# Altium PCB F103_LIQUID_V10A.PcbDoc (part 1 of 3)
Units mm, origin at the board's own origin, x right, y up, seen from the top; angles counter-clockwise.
Board outline 150.1 x 90.1 mm, 2 copper layers (TOP, BOTTOM), stack 1.6 mm thick; 78 components, 80 nets, 341 pads, 418 vias.
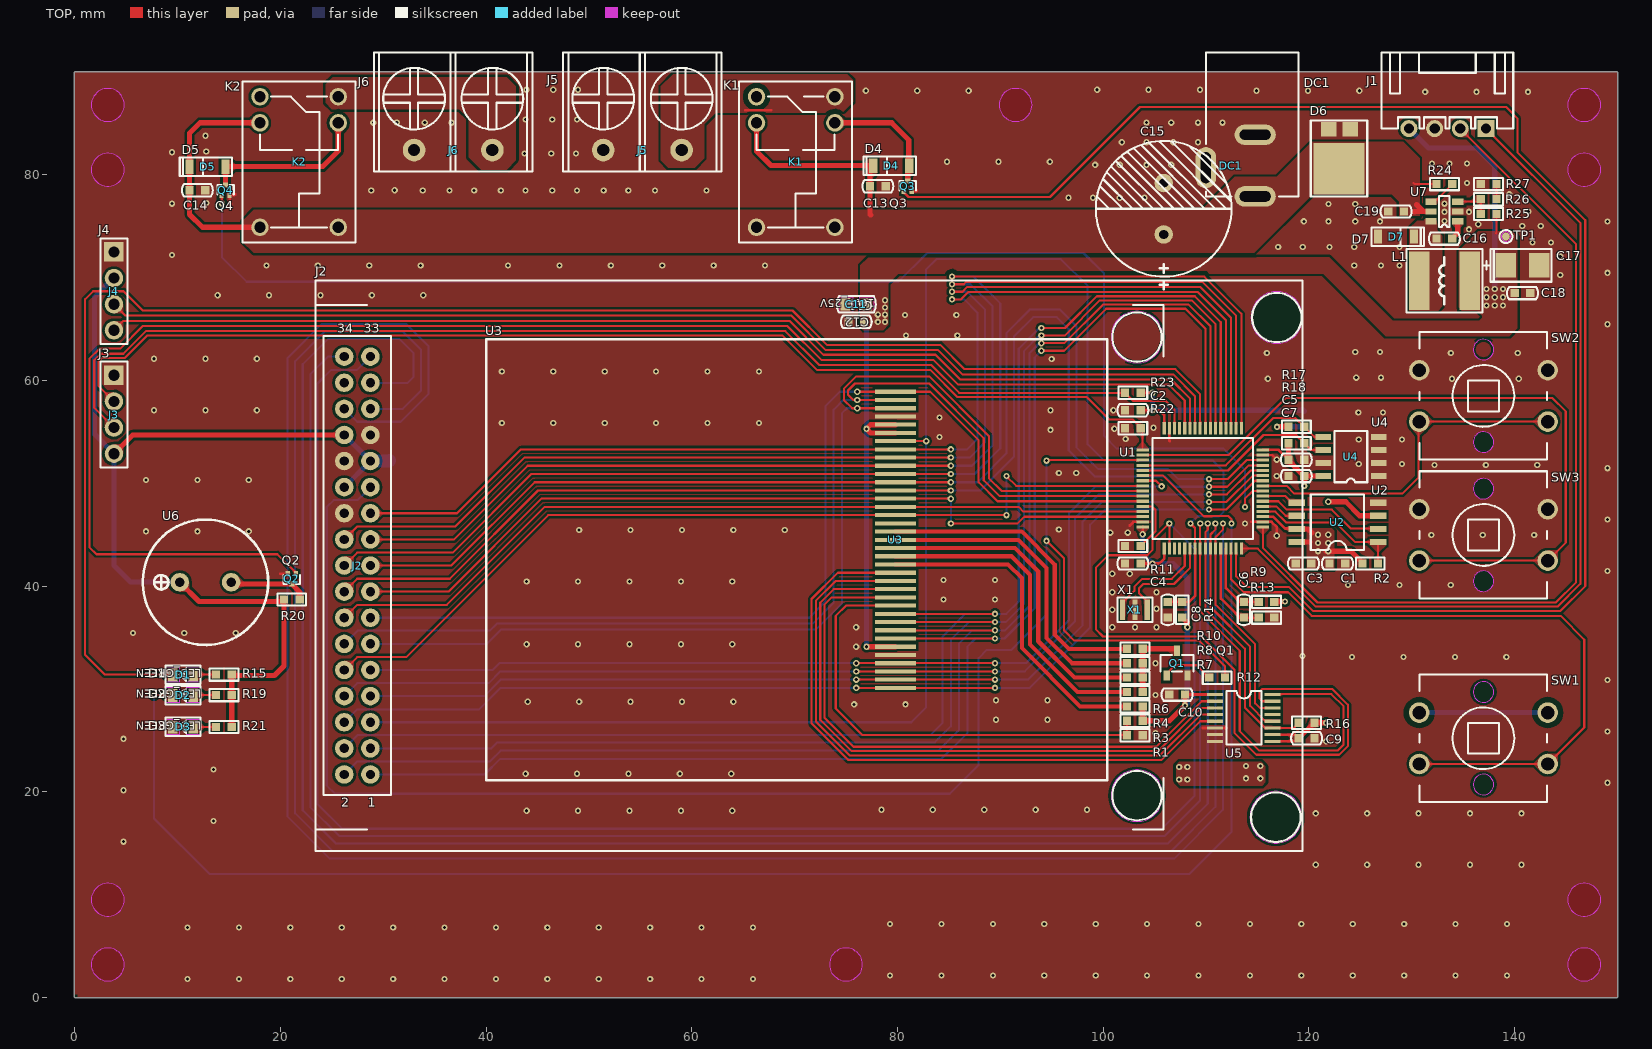
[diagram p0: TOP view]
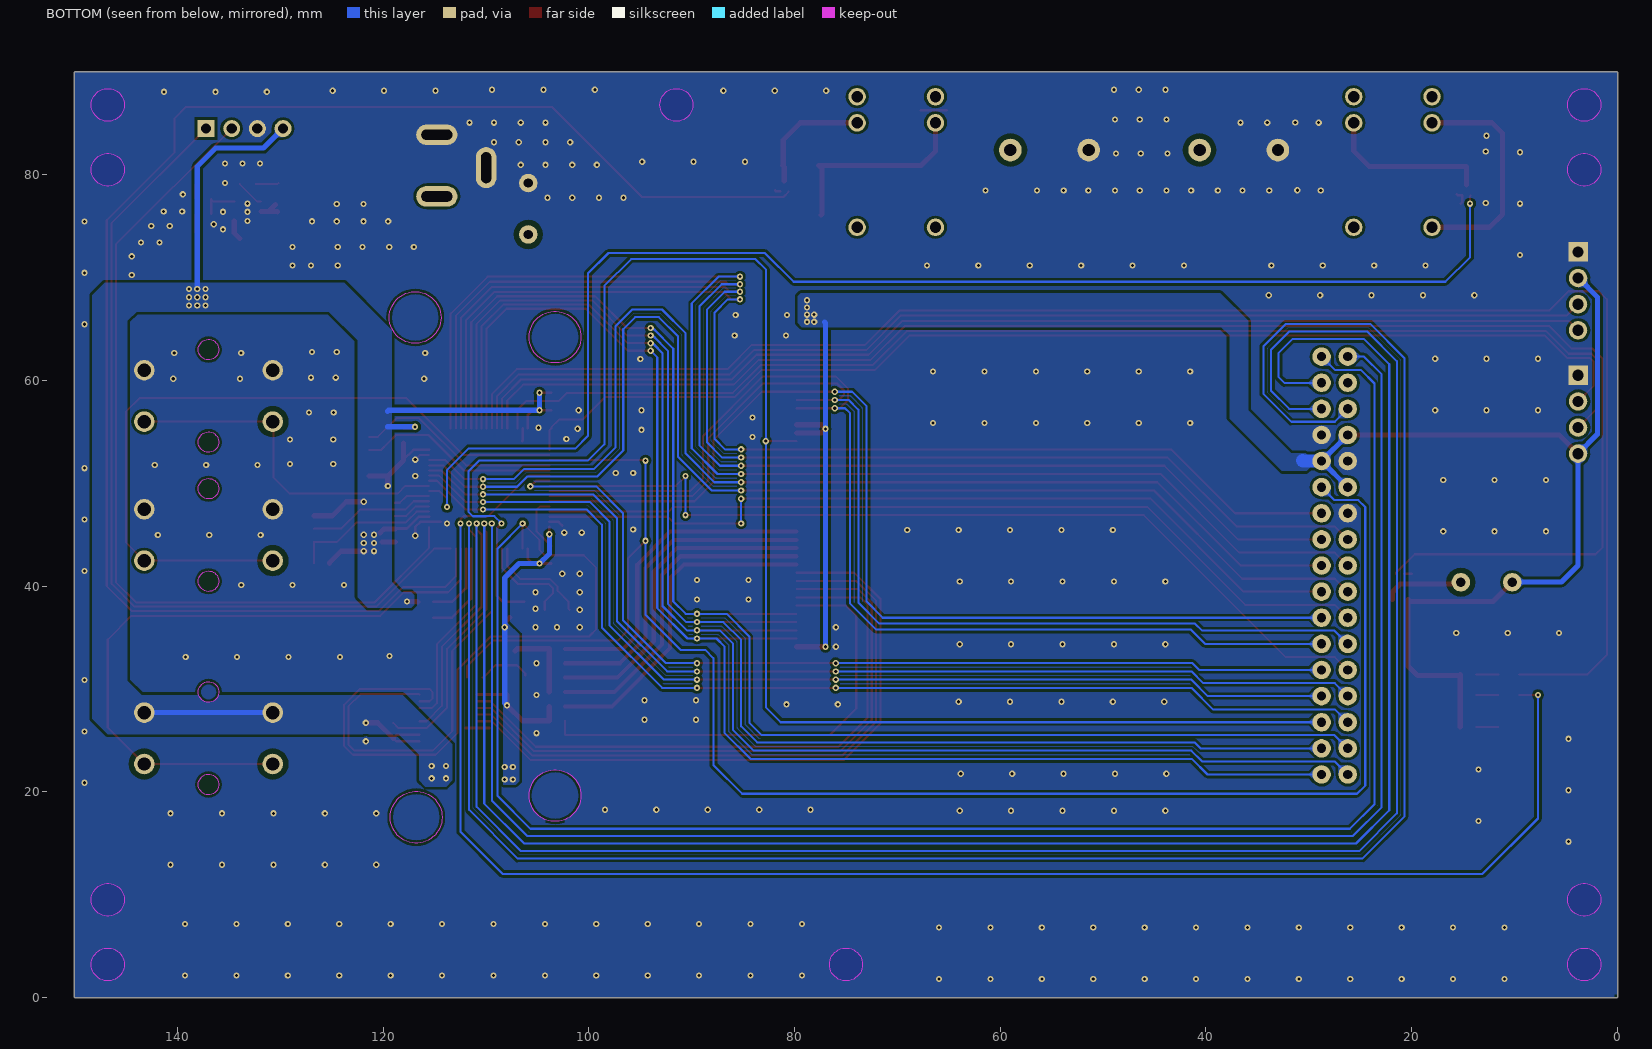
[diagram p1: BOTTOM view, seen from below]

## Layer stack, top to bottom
Top Solder: solder mask 0.0102, Solder Resist, Dk 3.5
TOP: signal copper 0.035
Dielectric 1: core 1.53, FR-4, Dk 4.5
BOTTOM: signal copper 0.035
Bottom Solder: solder mask 0.0102, Solder Resist, Dk 3.5

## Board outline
-0.05,0 0,-0.05 150,-0.05 150.05,0 150.05,90 150,90.05 0,90.05 -0.05,90
cut-out: 4.8,86.8 ccw(c3.2,86.8)
cut-out: 148.4,3.2 ccw(c146.8,3.2)
cut-out: 4.8,80.5 ccw(c3.2,80.5)
cut-out: 4.8,3.2 ccw(c3.2,3.2)
cut-out: 4.8,9.5 ccw(c3.2,9.5)
cut-out: 76.6,3.2 ccw(c75,3.2)
cut-out: 93.1,86.8 ccw(c91.5,86.8)
cut-out: 148.4,86.8 ccw(c146.8,86.8)
cut-out: 148.4,9.5 ccw(c146.8,9.5)
cut-out: 148.4,80.5 ccw(c146.8,80.5)

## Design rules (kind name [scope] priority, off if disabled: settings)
Clearance [All] p1: gap=0.254 ignorepadtopadclearanceinfootprint=FALSE except(0: Arc-Hole Track-Hole SMDPad-Hole THPad-Hole Via-Hole Fill-Hole Poly-Hole Region-Hole Text-Hole)
PlaneConnect [All] p1: planeconnectstyle=Direct reliefexpansion=0.508 reliefentries=4 reliefconductorwidth=0.254 reliefairgap=0.254
PolygonConnect [All] p1: connectstyle=Direct reliefconductorwidth=0.254 reliefentries=4 polygonreliefangle="90 Angle" airgapwidth=0.254
RoutingVias [All] p1: holewidth=0.711 width=1.27 viastyle="Through Hole" minholewidth=0.711 minwidth=1.27 maxholewidth=0.711 maxwidth=1.27
SolderMaskExpansion [All] p1: expansion=0.102
Width [All] p1: maxlimit=0.254 minlimit=0.254 preferedwidth=0.254 impedanceprofiledriven=TRUE minimp=61.210000 maximp=61.210000 favimp=61.210000
29 further rules are at their usual default settings.

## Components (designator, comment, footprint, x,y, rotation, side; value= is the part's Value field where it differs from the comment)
C1 "CAP NP_2_C0603_0.1UF_50V" C0603 122.8,42.2 r0 top
C2 "CAP NP_2_C0603_0.1UF_50V" C0603 102.9,57.1 r0 top
C3 "CAP NP_2_C0603_0.1UF_50V" C0603 119.5,42.2 r0 top
C4 "CAP NP_2_C0603_0.1UF_50V" C0603 102.9,42.2 r0 top
C5 "CAP NP_2_C0603_0.1UF_50V" C0603 118.8,52.3 r180 top
C6 "CAP NP_2_C0603_0.1UF_50V" C0603 113.7,37.7 r90 top
C7 "CAP NP_3_C0603_0.1UF_50V" C0603 118.8,50.7 r0 top
C8 "CAP NP_C0603_0.1UF_50V" C0603 106.3,37.7 r270 top
C9 "CAP NP_C0603_0.1UF_50V" C0603 119.8,25.202 r180 top
C10 "CAP NP_C0603_0.1UF_50V" C0603 107.2,29.452 r180 top
C11 "C_GENERIC_C0805_10UF_25V" C0805 76,67.4 r180 top
C12 "CAP NP_C0603_0.1UF_50V" C0603 76,65.7 r180 top
C13 "CAP NP_C0603_0.1UF_50V" C0603 78.1,78.9 r0 top
C14 "CAP NP_C0603_0.1UF_50V" C0603 11.912,78.5 r0 top
C15 "CAPT_100UF_3528_6R3V_10%_LXXXX_" CAP-5R0-13X27 105.9,76.7 r90 top
C16 "CAP NP_2_C0603_10NF_50V" C0603 133.2,73.8 r180 top
C17 "TMP_154254_C3528B_47UF_10V" C3528B 140.8,71.2 r180 top
C18 "CAP NP_C0603_0.1UF_25V" C0603 140.8,68.5 r0 top
C19 "CAP NP_C0603_0.1UF_25V" C0603 128.5,76.44 r180 top
D1 "LED_4_LED0805_LED_GREEN" LED0805 10.52,31.394 r180 top
D2 "LED_4_LED0805_LED_GREEN" LED0805 10.52,29.4 r180 top
D3 "LED_4_LED0805_LED_GREEN" LED0805 10.52,26.3 r180 top
D4 "DIODE13_7_SOD123_1N4148W-TP" SOD123 79.4,80.9 r0 top
D5 "DIODE13_7_SOD123_1N4148W-TP" SOD123 12.9,80.8 r0 top
D6 "DIODE13_6_TO-227A_V10P10" TO-227A 123,80.6 r180 top
D7 "DIODE13_0_SOD123_LMBR130FT1G" SOD123 128.5,74 r180 top
DC1 "DC005_DC005_DC005" DC005 114.8,83.9 r270 top
J1 "CONN RCPT 4_XHB-4AW_XHB-4AW" XHB-4AW 133.5,84.5 r180 top
J2 "CONN RCPT 17X2_1_TFTLCD_3R5_TFT" TFTLCD_3R5 26.2,62.322 r0 top
J3 "CONN RCPT 4_HEADER4X1-2R54-M_HE" HEADER4X1-2R54-M 3.8,60.5 r270 top
J4 "CONN RCPT 4_HEADER4X1-2R54-M_HE" HEADER4X1-2R54-M 3.8,72.5 r270 top
J5 "HDR_1_KF7R62-2P_KF7R62-2P" KF7R62-2P 55.2,82.412 r0 top
J6 "HDR_1_KF7R62-2P_KF7R62-2P" KF7R62-2P 36.8,82.412 r0 top
K1 "HF32FA-G/005-HSL1_0_HFD41_HFD41" HFD41 66.3,74.9 r90 top
K2 "HF32FA-G/005-HSL1_0_HFD41_HFD41" HFD41 18,74.9 r90 top
L1 "INDUCTOR_0_L6028_SLF6028T-4R7M1" L6028 133.2,69.7 r0 top
Q1 "L14G1/TO_1_SOT23-3_S8050" SOT23-3 107.2,32.5 r0 top
Q2 "DTC043ZMT2L_SOT723_DTC043ZMT2L" SOT723 21.1,40.7 r180 top
Q3 "DTC043ZMT2L_SOT723_DTC043ZMT2L" SOT723 81,78.9 r0 top
Q4 "DTC043ZMT2L_SOT723_DTC043ZMT2L" SOT723 14.65,78.5 r0 top
R1 "R_GENERIC_R0603_0R/NI" R0603 103.1,25.5 r0 top
R2 "R_GENERIC_R0603_10K" R0603 125.988,42.2 r0 top
R3 "R_GENERIC_R0603_0R/NI" R0603 103.1,26.9 r0 top
R4 "R_GENERIC_R0603_0R" R0603 103.1,28.3 r0 top
R6 "R_GENERIC_R0603_10R" R0603 103.1,29.7 r0 top
R7 "R_GENERIC_R0603_10R" R0603 103.1,31.1 r0 top
R8 "R_GENERIC_R0603_10R" R0603 103.1,32.5 r0 top
R9 "R_GENERIC_R0603_0R" R0603 115.9,38.462 r0 top
R10 "R_GENERIC_R0603_10R" R0603 103.1,33.9 r0 top
R11 "R_GENERIC_R0603_10K" R0603 102.9,43.9 r180 top
R12 "R_GENERIC_R0603_1K" R0603 111.1,31.1 r180 top
R13 "R_GENERIC_R0603_0R" R0603 115.9,36.938 r0 top
R14 "R_GENERIC_R0603_10K" R0603 107.7,37.7 r90 top
R15 "R_GENERIC_R0603_4.7K" R0603 14.5,31.394 r180 top
R16 "R_GENERIC_R0603_100K" R0603 119.8,26.7 r180 top
R17 "R_GENERIC_R0603_4.7K" R0603 118.8,55.49 r180 top
R18 "R_GENERIC_R0603_4.7K" R0603 118.8,53.9 r180 top
R19 "R_GENERIC_R0603_4.7K" R0603 14.5,29.4 r180 top
R20 "R_GENERIC_R0603_1K" R0603 21.1,38.7 r0 top
R21 "R_GENERIC_R0603_4.7K" R0603 14.5,26.3 r180 top
R22 "R_GENERIC_R0603_4.7K" R0603 102.9,55.35 r0 top
R23 "R_GENERIC_R0603_4.7K" R0603 102.9,58.8 r180 top
R24 "R_GENERIC_R0603_100K" R0603 133.2,79.1 r0 top
R25 "R_GENERIC_R0603_49.9K" R0603 137.5,76.2 r180 top
R26 "R_GENERIC_R0603_6.2K" R0603 137.5,77.64 r0 top
R27 "R_GENERIC_R0603_10K" R0603 137.5,79.1 r180 top
SW1 "SWITCH-SPST-4P_SW-B3F4055_KEY" SW-B3F4055 137,25.2 r0 top
SW2 "SWITCH-SPST-4P_SW-B3F4055_KEY" SW-B3F4055 137,58.5 r0 top
SW3 "SWITCH-SPST-4P_SW-B3F4055_KEY" SW-B3F4055 137,44.973 r0 top
TP1 "TESTPOINT_0_TP-0R75_TESTPOINT" TP-0R75 139.185,74 r0 top
U1 "STM32F103RXT6_LQFP64-10X10X0R5_" LQFP64-10X10X0R5 109.7,49.5 r0 top
U2 "W25QXX_SOIC8_208_W25Q64JVSSIQ" SOIC8_208 122.8,46.2 r90 top
U3 "TFT-2R4_TFT-2R4_TFT-2R4" TFT-2R4 79.8,30.102 r90 top
U4 "AT24C512_SOIC8_AT24C512C-SSHM-T" SOIC8 124.1,52.6 r90 top
U5 "XPT2046_TSSOP16_XPT2046" TSSOP16 113.7,27.177 r270 top
U6 "PS1240P02BT_PS1240P02BT_PS1240P" PS1240P02BT 12.7,40.374 r0 top
U7 "MP2359DJ-LF-Z_SOT23-6_MP2359DJ-" SOT23-6 133.2,76.44 r90 top
X1 "XTAL_5032_0_X-3P-3R2X1R3-SMD_CS" X-3P-3R2X1R3-SMD 103.1,37.7 r0 top

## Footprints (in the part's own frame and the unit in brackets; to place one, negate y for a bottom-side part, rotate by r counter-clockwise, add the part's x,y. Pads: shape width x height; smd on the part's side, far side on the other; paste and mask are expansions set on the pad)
C0603 [mm] "C0603"
  rect 0.8x0.8 smd: 1(-0.762,0) 2(0.762,0)
  silkscreen extent -1.51,-0.6 1.51,0.6, body extent -0.89,-0.38 0.89,0.38, height 3.81
C0805 [mm] "C0805"
  rect 1x1.2 smd: 1(-1.016,0) 2(1.016,0)
  TOP keep-out region: 0.356,0.762 1.676,0.762 1.676,-0.762 0.356,-0.762 0.356,0.762
  TOP keep-out region: -1.676,0.762 -0.356,0.762 -0.356,-0.762 -1.676,-0.762 -1.676,0.762
  silkscreen extent -1.9,-0.8 1.9,0.8, body extent -1,-0.6 1,0.6, height 3.81
C3528B [mm] "C3528B"
  rect 2x2.4 smd: 1(1.615,0) 2(-1.614,0)
  silkscreen extent -2.8,-1.6 3.8,1.6, body extent -1.8,-1.4 1.8,1.4, height 3.81
CAP-5R0-13X27 [mm] "CAP-5R0-13X27"
  round 1.8 / inner round 1.524 / far side round 1.8 hole 0.9: 1(-2.5,0) 2(2.5,0)
  silkscreen extent -7.8,-6.6 6.6,6.6, body extent -6.51,-6.51 6.51,6.51, height 3.81
DC005 [mm] "DC005"
  oval 2x4 / inner round 1.524 / far side oval 2x4 hole 1 slot 3 at 90 deg: 1(6,0) 2(0,0)
  oval 4x2 / inner round 1.524 / far side oval 4x2 hole 3 slot 1 at 90 deg: 3(3.2,-4.8)
  silkscreen extent -8,-4.8 6,4.2, body extent -8,-4.8 6,4.2, height 3.81
HEADER4X1-2R54-M [mm] "HEADER4X1-2R54-M"
  rect 1.9x1.9 / inner round 1.524 / far side rect 1.9x1.9 hole 1.1: 1(0,0)
  round 1.8 / inner round 1.524 / far side round 1.8 hole 1.1: 2(2.54,0) 3(5.08,0) 4(7.62,0)
  silkscreen extent -1.33,-1.8 8.97,1.3, body extent -1.23,-1.2 8.87,1.2, height 3.81
HFD41 [mm] "HFD41"
  round 1.7 / inner round 1.524 / far side round 1.7 hole 1.1: 1(0,-7.62) 2(10.16,-7.62) 3(12.7,-7.62) 4(12.7,0) 5(10.16,0) 6(0,0)
  silkscreen extent -1.5,-9.3 14.2,1.7, body extent -1.5,-9.31 14.2,1.69, height 3.81
KF7R62-2P [mm] "KF7R62-2P"
  round 2.2 / inner round 1.524 / far side round 2.2 hole 1.2: 1(-3.81,0) 2(3.81,0)
  silkscreen extent -7.71,-2.1 7.69,9.5, body extent -7.62,-2 7.58,9.4, height 3.81
L6028 [mm] "L6028"
  rect 2x5.7 smd: 1(-2.45,0) 2(2.45,0)
  silkscreen extent -3.7,-3.1 3.7,3.1, body extent -3,-3 3,3, height 3.81
LED0805 [mm] "LED0805"
  rect 0.9x1.3 smd: 1(-1,0) 2(1,0)
  TOP keep-out region: 0.356,0.762 1.676,0.762 1.676,-0.762 0.356,-0.762 0.356,0.762
  TOP keep-out region: -1.676,0.762 -0.356,0.762 -0.356,-0.762 -1.676,-0.762 -1.676,0.762
  silkscreen extent -1.7,-0.9 1.7,0.9, body extent -1,-0.6 1,0.6, height 3.81
LQFP64-10X10X0R5 [mm] "LQFP64-10X10X0R5"
  rect 0.3x1.2 smd: 1(-3.75,-5.85) 2(-3.25,-5.85) 3(-2.75,-5.85) 4(-2.25,-5.85) 5(-1.75,-5.85) 6(-1.25,-5.85) 7(-0.75,-5.85) 8(-0.25,-5.85) 9(0.25,-5.85) 10(0.75,-5.85) 11(1.25,-5.85) 12(1.75,-5.85) 13(2.25,-5.85) 14(2.75,-5.85) 15(3.25,-5.85) 16(3.75,-5.85) 33(3.75,5.85) 34(3.25,5.85) 35(2.75,5.85) 36(2.25,5.85) 37(1.75,5.85) 38(1.25,5.85) 39(0.75,5.85) 40(0.25,5.85) 41(-0.25,5.85) 42(-0.75,5.85) 43(-1.25,5.85) 44(-1.75,5.85) 45(-2.25,5.85) 46(-2.75,5.85) 47(-3.25,5.85) 48(-3.75,5.85)
  rect 1.2x0.3 smd: 17(5.85,-3.75) 18(5.85,-3.25) 19(5.85,-2.75) 20(5.85,-2.25) 21(5.85,-1.75) 22(5.85,-1.25) 23(5.85,-0.75) 24(5.85,-0.25) 25(5.85,0.25) 26(5.85,0.75) 27(5.85,1.25) 28(5.85,1.75) 29(5.85,2.25) 30(5.85,2.75) 31(5.85,3.25) 32(5.85,3.75) 49(-5.85,3.75) 50(-5.85,3.25) 51(-5.85,2.75) 52(-5.85,2.25) 53(-5.85,1.75) 54(-5.85,1.25) 55(-5.85,0.75) 56(-5.85,0.25) 57(-5.85,-0.25) 58(-5.85,-0.75) 59(-5.85,-1.25) 60(-5.85,-1.75) 61(-5.85,-2.25) 62(-5.85,-2.75) 63(-5.85,-3.25) 64(-5.85,-3.75)
  silkscreen extent -4.9,-7.21 4.9,4.9, body extent -5,-5 5,5, height 3.81
PS1240P02BT [mm] "PS1240P02BT"
  round 1.8 / inner round 1.524 / far side round 1.8 hole 0.9: 1(-2.5,0) 2(2.5,0)
  silkscreen extent -6.1,-6.1 6.1,6.1, body extent -6.11,-6.11 6.11,6.11, height 3.81
R0603 [mm] "R0603"
  rect 0.8x0.8 smd: 1(-0.762,0) 2(0.762,0)
  silkscreen extent -1.4,-0.6 1.4,0.6, body extent -0.89,-0.38 0.89,0.38, height 3.81
SOD123 [mm] "SOD123"
  rect 0.8x1.4 smd: 1(1.75,0) 2(-1.75,0)
  silkscreen extent -2.7,-0.9 2.4,0.9, body extent -1.7,-0.64 1.73,0.64, height 3.81
SOIC8 [mm] "SOIC8"
  rect 0.6x1.5 smd: 1(-1.9,-2.7) 2(-0.63,-2.7) 3(0.64,-2.7) 4(1.91,-2.7) 5(1.91,2.7) 6(0.64,2.7) 7(-0.63,2.7) 8(-1.9,2.7)
  silkscreen extent -2.5,-4.21 2.5,1.6, body extent -2.5,-2 2.5,2, height 3.81
SOIC8_208 [mm] "SOIC8_208"
  rect 0.6x1.6 smd: 1(-1.905,-3.95) 2(-0.635,-3.95) 3(0.635,-3.95) 4(1.905,-3.95) 5(1.905,3.95) 6(0.635,3.95) 7(-0.635,3.95) 8(-1.905,3.95)
  silkscreen extent -2.7,-5.51 2.7,2.6, body extent -2.7,-2.6 2.7,2.6, height 3.81
SOT23-3 [mm] "SOT23-3"
  rect 0.6x1 smd: 1(-1,-1.2) 2(1,-1.2) 3(0,1.2)
  silkscreen extent -1.6,-0.8 1.6,0.8, body extent -1.5,-0.7 1.5,0.7, height 3.81
SOT23-6 [mm] "SOT23-6"
  rect 0.6x1.1 smd: 1(-0.95,-1.3) 2(0,-1.3) 3(0.95,-1.3) 4(0.95,1.3) 5(0,1.3) 6(-0.95,1.3)
  silkscreen extent -1.52,-2.54 1.52,0.51, body extent -1.5,-0.8 1.5,0.8, height 3.81
SOT723 [mm] "SOT723"
  rect 0.4x0.5 smd: 1(-0.4,-0.5) 2(0.4,-0.5)
  rect 0.5x0.5 smd: 3(0,0.5)
  silkscreen extent -0.8,-0.4 0.8,0.5, body extent -0.65,-0.45 0.65,0.45, height 3.81
SW-B3F4055 [mm] "SW-B3F4055"
  round 2 / inner round 1.524 / far side round 2 hole 1.3: 1(-6.25,2.5) 2(6.25,2.5) 3(-6.25,-2.5) 4(6.25,-2.5)
  Multi-Layer keep-out circle w0.025: c0,-4.5 r1
  Multi-Layer keep-out circle w0.025: c0,4.5 r1
  silkscreen extent -6.2,-6.2 6.2,6.2, body extent -6,-6 6,6, height 3.81
TFT-2R4 [mm] "TFT-2R4"
  rect 0.4x4 smd: 1(0,0) 2(0.8,0) 3(1.6,0) 4(2.4,0) 5(3.2,0) 6(4,0) 7(4.8,0) 8(5.6,0) 9(6.4,0) 10(7.2,0) 11(8,0) 12(8.8,0) 13(9.6,0) 14(10.4,0) 15(11.2,0) 16(12,0) 17(12.8,0) 18(13.6,0) 19(14.4,0) 20(15.2,0) 21(16,0) 22(16.8,0) 23(17.6,0) 24(18.4,0) 25(19.2,0) 26(20,0) 27(20.8,0) 28(21.6,0) 29(22.4,0) 30(23.2,0) 31(24,0) 32(24.8,0) 33(25.6,0) 34(26.4,0) 35(27.2,0) 36(28,0) 37(28.8,0)
  silkscreen extent -9,-20.6 33.9,39.8, body extent -8.9,-20.5 33.8,39.7, height 3.81
TFTLCD_3R5 [mm] "TFTLCD_3R5"
  round 1.8 / inner round 1.524 / far side round 1.8 hole 0.9: 1(2.54,-40.64) 2(0,-40.64) 3(2.54,-38.1) 4(0,-38.1) 5(2.54,-35.56) 6(0,-35.56) 7(2.54,-33.02) 8(0,-33.02) 9(2.54,-30.48) 10(0,-30.48) 11(2.54,-27.94) 12(0,-27.94) 13(2.54,-25.4) 14(0,-25.4) 15(2.54,-22.86) 16(0,-22.86) 17(2.54,-20.32) 18(0,-20.32) 19(2.54,-17.78) 20(0,-17.78) 21(2.54,-15.24) 22(0,-15.24) 23(2.54,-12.7) 24(0,-12.7) 25(2.54,-10.16) 26(0,-10.16) 27(2.54,-7.62) 28(0,-7.62) 29(2.54,-5.08) 30(0,-5.08) 31(2.54,-2.54) 32(0,-2.54) 33(2.54,0) 34(0,0)
  Multi-Layer keep-out circle w0.025: c90.6,-44.8 r2.518
  Multi-Layer keep-out circle w0.025: c77.1,-42.7 r2.518
  Multi-Layer keep-out circle w0.025: c90.7,3.8 r2.518
  Multi-Layer keep-out circle w0.025: c77.1,1.9 r2.518
  silkscreen extent -2.8,-48.1 93.2,7.4, body extent -1.78,-42.55 4.44,1.91, height 3.81
TO-227A [mm] "TO-227A"
  rect 1.5x1.4 smd: 1(1.04,-3.85) 2(-1.04,-3.85)
  rect 5x5 smd: 3(0.05,0)
  silkscreen extent -2.7,-4.7 2.8,2.7, body extent -2.15,-4.1 2.2,2.05, height 3.81
TP-0R75 [mm] "TP-0R75"
  round 0.75 smd: 1(0,0)
  TOP keep-out circle w0.025: c0,0 r0.457
  silkscreen extent -0.63,-0.63 0.64,0.63, body extent -0.47,-0.47 0.47,0.47, height 3.81
TSSOP16 [mm] "TSSOP16"
  rect 0.3x1.55 smd: 1(-2.275,-2.8) 2(-1.625,-2.8) 3(-0.975,-2.8) 4(-0.325,-2.8) 5(0.325,-2.8) 6(0.975,-2.8) 7(1.625,-2.8) 8(2.275,-2.8) 9(2.275,2.8) 10(1.625,2.8) 11(0.975,2.8) 12(0.325,2.8) 13(-0.325,2.8) 14(-0.975,2.8) 15(-1.625,2.8) 16(-2.275,2.8)
  silkscreen extent -2.6,-4.31 2.6,1.7, body extent -2.5,-1.7 2.5,1.7, height 3.81
X-3P-3R2X1R3-SMD [mm] "X-3P-3R2X1R3-SMD"
  rect 0.5x2 smd: 1(-1.2,0) 2(0,0) 3(1.2,0)
  silkscreen extent -1.7,-1.2 1.7,1.2, body extent -1.6,-0.65 1.6,0.65, height 3.81
XHB-4AW [mm] "XHB-4AW"
  rect 1.65x1.65 / inner round 1.524 / far side rect 1.65x1.65 hole 1: 1(-3.75,0)
  round 1.65 / inner round 1.524 / far side round 1.65 hole 1: 2(-1.25,0) 3(1.25,0) 4(3.75,0)
  silkscreen extent -6.4,-7.4 6.4,0, body extent -6.3,-7.3 6.3,-0.1, height 3.81

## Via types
v1: diameter 0.61, hole 0.305, TOP to BOTTOM, tented both sides, 418 vias

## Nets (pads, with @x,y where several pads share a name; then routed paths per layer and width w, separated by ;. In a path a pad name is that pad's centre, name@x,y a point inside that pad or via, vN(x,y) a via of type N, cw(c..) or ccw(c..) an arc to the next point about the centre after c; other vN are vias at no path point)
BOOT0: R11.1 U1.60 | length 5.5
  TOP w0.203: R11.1@103.662,43.9 105.1,45.338 105.1,47.4 104.75,47.75 U1.60@103.85,47.75
CTL_BEEP: Q2.1 U1.44 | length 153.1
  TOP w0.203: Q2.1@21.5,41.2 21.5,41.281 19.681,43.1 2.1,43.1 1.406,43.794 1.406,62.106 2.4,63.1 4.4,63.1 6.6,65.3 69.3,65.3 72.6,62 83.5,62 85.9,59.6 106.4,59.6 107.95,58.05 U1.44@107.95,55.35
CTL_RELAY1: Q3.1 U1.15 | length 151.3
  TOP w0.203: Q3.1@80.6,78.4 80.6,78.319 81.074,77.845 94.845,77.845 103.6,86.6 139.2,86.6 140.3,85.5 140.3,82.2 146.9,75.6 146.9,40 144.494,37.594 120.406,37.594 118.1,39.9 114,39.9 112.95,40.95 U1.15@112.95,43.65
CTL_RELAY2: Q4.1 U1.24 | length 132.1
  TOP w0.203: Q4.1@14.25,78 14.3,77.95 v1(14.3,77.2) ; v1(113.8,47.7) 113.8,48.5 114.55,49.25 U1.24@115.55,49.25
  BOTTOM w0.203: v1(14.3,77.2) 14.3,72 16.7,69.6 80.1,69.6 82.9,72.4 98.1,72.4 100.1,70.4 100.1,54.6 101.3,53.4 111.7,53.4 113.8,51.3 v1(113.8,47.7)
F_CS: R2.2 U1.20 U2.1 | length 14.5
  TOP w0.203: U1.20@115.55,47.25 116.75,47.25 117.8,46.2 122.6,46.2 124.5,44.3 126.745,44.3 U2.1@126.75,44.295 R2.2@126.75,42.2
GND: C1.2 C2.1 C3.1 C4.1 C5.1 C7.1 C8.2 C9.1 C10.2 C11.2 C12.2 C13.2 C14.2 C15.2 C17.2 C18.2 C19.2 D3.2 D6.1 D6.2 D7.1 DC1.2 DC1.3 J1.3 J2.22 J2.26 J2.27 J3.1 J4.1 J5.1 J6.1 Q1.2 Q2.2 Q3.2 Q4.2 R1.2 R11.2 R13.2 R22.1 R27.2 SW2.1 SW2.2 SW3.1 SW3.2 U1.18 U1.31 U1.47 U1.63 U2.4 U3.5 U3.34 U4.1 U4.2 U4.3 U4.4 U4.7 U5.6 U5.7 U5.8 U7.2 X1.2 | length 12.7
  TOP w0.203: U1.31@115.55,52.75 116.45,52.75 v1(116.9,52.3)
  TOP w0.254: 15.2,77.2 15.05,77.35 Q4.2@15.05,78 15.5,78 15.6,78.1 ; 20,41.2 Q2.2@20.7,41.2 ; Q3.2@81.4,78.4 81.8,78.4 81.9,78.5 ; 102.6,45.9 102.95,46.25 U1.63@103.85,46.25 ; U1.47@106.45,55.35 106.45,54.15 106.5,54.1 ; 109.7,26.2 109.702,26.202 U5.6@110.9,26.202 111.998,26.202 112,26.2 ; 114.409,46.25 U1.18@115.55,46.25 116.403,46.25 116.9,45.753 v1(116.9,44.9)
  other v1: 10.954,1.791 15.954,1.791 20.954,1.791 25.954,1.791 30.954,1.791 35.954,1.791 40.954,1.791 45.954,1.791 50.954,1.791 55.954,1.791 60.954,1.791 65.954,1.791 79.287,2.128 84.287,2.128 89.287,2.128 94.287,2.128 99.287,2.128 104.287,2.128 109.287,2.128 114.287,2.128 119.287,2.128 124.287,2.128 129.287,2.128 134.287,2.128 139.287,2.128 10.954,6.791 15.954,6.791 20.954,6.791 25.954,6.791 30.954,6.791 35.954,6.791 40.954,6.791 45.954,6.791 50.954,6.791 55.954,6.791 60.954,6.791 65.954,6.791 79.287,7.128 84.287,7.128 89.287,7.128 94.287,7.128 99.287,7.128 104.287,7.128 109.287,7.128 114.287,7.128 119.287,7.128 124.287,7.128 129.287,7.128 134.287,7.128 139.287,7.128 120.69,12.9 125.69,12.9 130.69,12.9 135.69,12.9 140.69,12.9 4.727,15.144 13.479,17.163 120.69,17.9 125.69,17.9 130.69,17.9 135.69,17.9 140.69,17.9 43.943,18.146 48.943,18.146 53.943,18.146 58.943,18.146 63.943,18.146 78.442,18.246 83.443,18.246 88.443,18.246 93.443,18.246 98.443,18.246 4.727,20.144 149.074,20.87 43.843,21.746 48.843,21.746 53.843,21.746 58.843,21.746 63.843,21.746 13.479,22.163 121.7,24.9 4.727,25.144 105.1,25.7 149.074,25.87 89.59,27 94.59,27 75.79,28.5 80.79,28.5 44.043,28.746 49.043,28.746 54.043,28.746 59.043,28.746 64.043,28.746 89.59,28.9 94.59,28.9 105.1,29.4 149.074,30.87 105.1,32.5 124.225,33.096 129.225,33.096 134.225,33.096 139.225,33.096 119.4,33.2 75.99,34.1 43.943,34.346 48.943,34.346 53.943,34.346 58.943,34.346 63.943,34.346 5.643,35.446 10.643,35.446 15.643,35.446 75.99,36 100.9,36 103.1,36 105.2,36 100.9,37.7 105.2,37.8 84.49,38.7 89.49,38.7 100.9,39.4 105.2,39.4 123.825,40.096 128.825,40.096 133.825,40.096 43.943,40.446 48.943,40.446 53.943,40.446 58.943,40.446 63.943,40.446 84.49,40.6 89.49,40.6 100.9,41.2 102.6,41.2 149.074,41.47 131.93,44.974 136.93,44.974 141.93,44.974 100.7,45.2 102.4,45.2 6.915,45.327 11.915,45.327 16.915,45.327 49.043,45.446 54.043,45.446 59.043,45.446 64.043,45.446 69.043,45.446 95.7,45.5 113.8,46.1 149.074,46.47 6.915,50.327 11.915,50.327 16.915,50.327 116.9,50.7 95.7,51 97.4,51 149.074,51.47 132.23,51.774 137.23,51.774 142.23,51.774 124.874,51.87 129.074,51.87 124.874,54.27 129.074,54.27 102.2,54.3 84.09,54.5 94.89,55.2 101.1,55.3 104.9,55.4 41.53,55.874 46.53,55.874 51.53,55.874 56.53,55.874 61.53,55.874 66.53,55.874 84.09,56.4 124.83,56.874 127.23,56.874 7.701,57.108 12.701,57.108 17.701,57.108 94.89,57.1 101,57.1 116.03,60.174 133.93,60.174 140.43,60.174 124.63,60.274 127.03,60.274 41.53,60.874 46.53,60.874 51.53,60.874 56.53,60.874 61.53,60.874 66.53,60.874 7.701,62.108 12.701,62.108 17.701,62.108 95,62.1 115.93,62.674 133.83,62.674 140.33,62.674 124.53,62.774 126.93,62.774 80.83,64.374 85.83,64.374 149.074,65.47 80.73,66.374 85.73,66.374 13.884,68.29 18.884,68.29 23.884,68.29 28.884,68.29 33.884,68.29 144.474,70.27 149.074,70.47 18.63,71.174 23.63,71.174 28.63,71.174 33.63,71.174 42.13,71.174 47.13,71.174 52.13,71.174 57.13,71.174 62.13,71.174 67.13,71.174 124.43,71.174 127.03,71.174 128.83,71.174 144.474,72.07 9.44,72.2 117.03,72.974 119.43,72.974 122.03,72.974 124.43,72.974 128.83,72.974 141.77,73.426 143.57,73.426 135.6,74.7 140.77,75.026 142.57,75.026 136.5,75.2 119.53,75.474 121.93,75.474 124.53,75.474 126.93,75.474 149.074,75.47 133.2,75.5 133.2,76.4 135.6,76.4 139.57,76.426 141.37,76.426 121.93,77.174 124.53,77.174 9.44,77.2 133.2,77.2 12.774,77.27 96.63,77.774 99.03,77.774 101.63,77.774 104.03,77.774 139.5,78.1 28.83,78.474 33.83,78.474 36.43,78.474 38.83,78.474 41.43,78.474 43.83,78.474 46.43,78.474 48.83,78.474 51.43,78.474 53.83,78.474 56.43,78.474 61.43,78.474 31.1,78.5 135.4,79.2 99.23,80.974 101.63,80.974 104.23,80.974 106.63,80.974 132,81.1 133.7,81.1 135.4,81.1 84.83,81.274 89.83,81.274 94.83,81.274 43.73,82.074 46.33,82.074 48.73,82.074 9.44,82.2 12.774,82.27 101.83,83.174 104.23,83.174 106.83,83.174 109.23,83.174 12.7,83.8 29.03,85.074 34.03,85.074 36.63,85.074 104.23,85.074 106.63,85.074 109.23,85.074 111.63,85.074 31.3,85.1 43.83,85.374 46.43,85.374 48.83,85.374 131.33,88.074 136.33,88.074 141.33,88.074 76.93,88.174 81.93,88.174 86.93,88.174 114.93,88.174 119.93,88.174 124.93,88.174 43.93,88.274 46.53,88.274 48.93,88.274 99.43,88.274 104.43,88.274 109.43,88.274
IIC_SCL: R18.1 U1.53 U4.6 | length 19.6
  TOP w0.203: U1.53@103.85,51.25 112.157,51.25 115.604,54.696 118.766,54.696 R18.1@119.562,53.9 120.222,53.24 U4.6@121.4,53.24
IIC_SDA: R17.1 U1.52 U4.5 | length 20.2
  TOP w0.203: U1.52@103.85,51.75 111.95,51.75 116.55,56.35 118.702,56.35 R17.1@119.562,55.49 120.542,54.51 U4.5@121.4,54.51
IM0: R1.1 R3.1 U3.11 | length 46
  TOP w0.203: U3.11@79.8,38.102 75.002,38.102 74,37.1 74,28.1 76.6,25.5 R1.1@102.338,25.5 R3.1@102.338,26.9
KEY0: SW2.3 SW2.4 U1.25 | length 34
  TOP w0.203: U1.25@115.55,49.75 117.85,49.75 118.6,49 129.1,49 130.7,50.6 130.7,55.95 SW2.3@130.75,56 SW2.4@143.25,56
KEY1: SW3.3 SW3.4 U1.50 | length 71.7
  TOP w0.203: U1.50@103.85,52.75 112.231,52.75 117.781,58.3 143.7,58.3 145,57 145,44.224 SW3.4@143.25,42.473 SW3.3@130.75,42.473
LCD_BL: J2.23 R12.1 U1.51 | length 167.8
  TOP w0.203: v1(94.5,44.4) 96.2,42.7 96.2,35.7 97.206,34.694 109.375,34.694 111.862,32.207 R12.1@111.862,31.1 ; v1(94.5,52.2) 94.55,52.25 U1.51@103.85,52.25
  BOTTOM w0.203: J2.23@28.74,49.622 27.484,48.366 25.166,48.366 24.5,47.7 24.5,20.6 25.3,19.8 85.1,19.8 87.9,22.6 87.9,33 88.7,33.8 91.1,33.8 94.5,37.2 v1(94.5,44.4) v1(94.5,52.2)
LCD_CS: J2.1 U1.40 U3.7 | length 139.4
  TOP w0.203: U3.7@79.8,34.902 v1(89.5,34.902) ; v1(94,62.89) 96.212,62.89 100.296,66.974 108.026,66.974 109.95,65.05 U1.40@109.95,55.35
  BOTTOM w0.203: J2.1@28.74,21.682 39.84,21.682 41.358,23.2 84.294,23.2 86.8,25.706 86.8,34.106 87.596,34.902 v1(89.5,34.902) 90.412,34.902 93.362,37.853 93.362,62.253 v1(94,62.89)
LCD_D0: J2.6 U1.26 U3.1 | length 104.9
  TOP w0.203: v1(76,30.102) U3.1@79.8,30.102 v1(89.5,30.102) ; v1(110.3,47.454) 111.982,47.454 114.779,50.25 U1.26@115.55,50.25
  BOTTOM w0.203: J2.6@26.2,26.762 27.456,28.018 39.318,28.018 41.402,30.102 v1(76,30.102) ; v1(89.5,30.102) 92.869,30.102 98.746,35.979 98.746,45.979 100.221,47.454 v1(110.3,47.454)
LCD_D1: J2.7 U1.27 U3.2 | length 101.6
  TOP w0.203: v1(76,30.902) U3.2@79.8,30.902 v1(89.5,30.902) ; v1(110.3,48.19) 112.012,48.19 114.572,50.75 U1.27@115.55,50.75
  BOTTOM w0.203: J2.7@28.74,29.302 39.802,29.302 41.402,30.902 v1(76,30.902) ; v1(89.5,30.902) 92.702,30.902 98.01,36.21 98.01,46.284 99.916,48.19 v1(110.3,48.19)
LCD_D2: J2.8 U1.28 U3.3 | length 104.3
  TOP w0.203: v1(76,31.702) U3.3@79.8,31.702 v1(89.5,31.702) ; v1(110.3,48.927) 112.041,48.927 114.364,51.25 U1.28@115.55,51.25
  BOTTOM w0.203: J2.8@26.2,29.302 27.456,30.558 40.258,30.558 41.402,31.702 v1(76,31.702) ; v1(89.5,31.702) 92.386,31.702 97.273,36.59 97.273,46.59 99.61,48.927 v1(110.3,48.927)
LCD_D3: J2.9 U1.55 U3.4 | length 92.5
  TOP w0.203: v1(76,32.502) U3.4@79.8,32.502 v1(89.498,32.502) ; U1.55@103.85,50.25 105.15,50.25 v1(105.7,49.7)
  BOTTOM w0.203: J2.9@28.74,31.842 40.642,31.842 41.302,32.502 v1(76,32.502) ; v1(89.498,32.502) 92.502,32.502 96.706,36.706 96.706,47.106 99.3,49.7 v1(105.7,49.7)
LCD_D4: J2.10 U1.56 U3.22 | length 88.1
  TOP w0.203: J2.10@26.2,31.842 27.456,33.098 32.231,33.098 46.036,46.902 U3.22@79.8,46.902 v1(90.6,46.902) ; v1(90.6,50.7) 91.55,49.75 U1.56@103.85,49.75
  BOTTOM w0.203: v1(90.6,46.902) v1(90.6,50.7)
LCD_D5: J2.11 U1.57 U3.35 | length 110.7
  TOP w0.203: U3.35@79.8,57.302 v1(76.1,57.302) 75.598,57.302 74.794,58.106 74.794,59.194 76,60.4 83.1,60.4 88.9,54.6 88.9,50.5 90.15,49.25 U1.57@103.85,49.25
  BOTTOM w0.203: J2.11@28.74,34.382 40.082,34.382 41.491,35.791 72.091,35.791 74.6,38.3 74.6,56.799 75.103,57.302 v1(76.1,57.302)
LCD_D6: J2.12 U1.58 U3.36 | length 111.8
  TOP w0.203: U3.36@79.8,58.102 v1(76.1,58.102) 75.698,58.102 75.2,58.6 75.2,59.025 75.875,59.7 83.093,59.7 88.4,54.393 88.4,50.293 89.943,48.75 U1.58@103.85,48.75
  BOTTOM w0.203: J2.12@26.2,34.382 27.484,35.666 40.366,35.666 41.056,36.356 71.756,36.356 73.8,38.4 73.8,57.169 74.733,58.102 v1(76.1,58.102)
LCD_D7: J2.13 U1.59 U3.37 | length 102.2
  TOP w0.203: v1(76.1,58.902) U3.37@79.8,58.902 83.184,58.902 87.9,54.186 87.9,50.086 89.736,48.25 U1.59@103.85,48.25
  BOTTOM w0.203: J2.13@28.74,36.922 71.422,36.922 73,38.5 73,57.5 74.402,58.902 v1(76.1,58.902)
LCD_D8: J2.14 U1.61 U3.23 | length 82.3
  TOP w0.203: J2.14@26.2,36.922 27.456,38.178 36.18,38.178 45.704,47.702 U3.23@79.8,47.702 91.798,47.702 92.25,47.25 U1.61@103.85,47.25
LCD_D9: J2.15 U1.62 U3.24 | length 81.5
  TOP w0.203: J2.15@28.74,39.462 36.333,39.462 45.373,48.502 U3.24@79.8,48.502 v1(85.2,48.502) ; v1(85.2,46.1) 91.7,46.1 92.35,46.75 U1.62@103.85,46.75
  BOTTOM w0.203: v1(85.2,46.1) v1(85.2,48.502)
LCD_D10: J2.16 U1.29 U3.25 | length 121.9
  TOP w0.203: J2.16@26.2,39.462 27.456,40.718 36.457,40.718 45.041,49.302 U3.25@79.8,49.302 v1(85.2,49.302) ; v1(110.3,49.663) 112.071,49.663 114.157,51.75 U1.29@115.55,51.75
  BOTTOM w0.203: v1(85.2,49.302) 88.044,49.302 91.337,52.595 91.337,64.295 93.205,66.163 95.495,66.163 96.663,64.995 96.663,53.195 99.195,50.663 105.995,50.663 106.995,49.663 v1(110.3,49.663)
LCD_D11: J2.17 U1.30 U3.26 | length 118.5
  TOP w0.203: J2.17@28.74,42.002 36.61,42.002 44.71,50.102 U3.26@79.8,50.102 v1(85.2,50.102) ; v1(110.3,50.4) 112.1,50.4 113.95,52.25 U1.30@115.55,52.25
  BOTTOM w0.203: v1(85.2,50.102) 85.202,50.1 87.8,50.1 90.6,52.9 90.6,64.6 92.9,66.9 95.8,66.9 97.4,65.3 97.4,53.5 99.5,51.4 106.3,51.4 107.3,50.4 v1(110.3,50.4)
LCD_D12: J2.18 U1.33 U3.27 | length 129.2
  TOP w0.203: J2.18@26.2,42.002 27.456,43.258 36.734,43.258 44.379,50.902 U3.27@79.8,50.902 v1(85.2,50.902) ; v1(85.3,70.1) 109.85,70.1 113.45,66.5 U1.33@113.45,55.35
  BOTTOM w0.203: v1(85.2,50.902) 87.502,50.902 90,53.4 90,67.5 87.4,70.1 v1(85.3,70.1)
LCD_D13: J2.19 U1.34 U3.28 | length 122.7
  TOP w0.203: J2.19@28.74,44.542 36.887,44.542 44.047,51.702 U3.28@79.8,51.702 v1(85.2,51.702) ; v1(85.3,69.363) 86.463,69.363 86.7,69.6 109.643,69.6 112.95,66.293 U1.34@112.95,55.35
  BOTTOM w0.203: v1(85.2,51.702) 87.26,51.702 89.263,53.705 89.263,67.195 87.095,69.363 v1(85.3,69.363)
LCD_D14: J2.20 U1.35 U3.29 | length 122.4
  TOP w0.203: J2.20@26.2,44.542 27.456,45.798 37.012,45.798 43.716,52.502 U3.29@79.8,52.502 v1(85.2,52.502) ; v1(85.3,68.627) 86.327,68.627 86.8,69.1 109.436,69.1 112.45,66.086 U1.35@112.45,55.35
  BOTTOM w0.203: v1(85.2,52.502) 87.018,52.502 88.527,54.01 88.527,66.89 86.79,68.627 v1(85.3,68.627)
LCD_D15: J2.21 U1.36 U3.30 | length 115.9
  TOP w0.203: J2.21@28.74,47.082 37.165,47.082 43.385,53.302 U3.30@79.8,53.302 v1(85.2,53.302) ; v1(85.3,67.89) 86.19,67.89 86.9,68.6 109.229,68.6 111.95,65.879 U1.36@111.95,55.35
  BOTTOM w0.203: v1(85.2,53.302) 86.777,53.302 87.79,54.316 87.79,66.584 86.484,67.89 v1(85.3,67.89)
LCD_LEDA: R4.1 U3.16 | length 32.2
  TOP w0.4: U3.16@79.8,42.102 90.772,42.102 92.1,40.774 92.1,33.974 97.774,28.3 R4.1@102.338,28.3
LCD_LEDK1: R6.1 U3.17 | length 32
  TOP w0.4: U3.17@79.8,42.902 91.104,42.902 92.9,41.106 92.9,34.306 97.506,29.7 R6.1@102.338,29.7
LCD_LEDK2: R7.1 U3.18 | length 31.7
  TOP w0.4: U3.18@79.8,43.702 91.435,43.702 93.7,41.437 93.7,34.637 97.237,31.1 R7.1@102.338,31.1
LCD_LEDK3: R8.1 U3.19 | length 31.5
  TOP w0.4: U3.19@79.8,44.502 91.767,44.502 94.5,41.769 94.5,34.969 96.969,32.5 R8.1@102.338,32.5
LCD_LEDK4: R10.1 U3.20 | length 31.2
  TOP w0.4: U3.20@79.8,45.302 92.098,45.302 95.3,42.1 95.3,35.3 96.7,33.9 R10.1@102.338,33.9
LCD_RD: J2.4 U1.37 U3.10 | length 143.9
  TOP w0.203: U3.10@79.8,37.302 v1(89.5,37.302) ; v1(94,65.1) 96.3,65.1 99.394,68.194 108.928,68.194 111.45,65.672 U1.37@111.45,55.35
  BOTTOM w0.203: J2.4@26.2,24.222 27.484,25.506 83.206,25.506 84.4,26.7 84.4,35.1 86.602,37.302 v1(89.5,37.302) 90.602,37.302 91.8,38.5 91.8,63.097 93.726,65.024 93.924,65.024 v1(94,65.1)
LCD_RS: J2.2 U1.39 U3.8 | length 143
  TOP w0.203: U3.8@79.8,35.702 v1(89.5,35.702) ; v1(94,63.627) 96.241,63.627 99.995,67.381 108.326,67.381 110.45,65.257 U1.39@110.45,55.35
  BOTTOM w0.203: J2.2@26.2,21.682 27.456,22.938 40.36,22.938 41.423,24 83.963,24 86,26.037 86,34.437 87.265,35.702 v1(89.5,35.702) 90.475,35.702 92.842,38.068 92.842,62.666 93.726,63.551 93.924,63.551 v1(94,63.627)
LCD_WR: J2.3 U1.38 U3.9 | length 140.4
  TOP w0.203: U3.9@79.8,36.502 v1(89.5,36.502) ; v1(94,64.363) 96.271,64.363 99.694,67.787 108.627,67.787 110.95,65.464 U1.38@110.95,55.35
  BOTTOM w0.203: J2.3@28.74,24.222 40.522,24.222 41.1,24.8 83.631,24.8 85.2,26.369 85.2,34.769 86.933,36.502 v1(89.5,36.502) 90.539,36.502 92.321,38.284 92.321,62.882 93.726,64.287 93.924,64.287 v1(94,64.363)
LED0: D1.2 U1.41 | length 160.1
  TOP w0.203: D1.2@9.52,31.394 9.514,31.4 2.9,31.4 1,33.3 1,67.9 1.776,68.676 4.724,68.676 6.6,66.8 69.8,66.8 73.139,63.461 84.161,63.461 86.522,61.1 107.022,61.1 109.45,58.672 U1.41@109.45,55.35
LED1: D2.2 U1.54 | length 163.4
  TOP w0.203: v1(7.7,29.4) D2.2@9.52,29.4 ; U1.54@103.85,50.75 105.85,50.75 109.807,46.793 110.574,46.793 110.58,46.8 112.2,46.8 112.5,46.5 v1(112.5,46.1)
  BOTTOM w0.203: v1(7.7,29.4) 7.7,17.4 13.1,12 108.4,12 112.5,16.1 v1(112.5,46.1)
N17026623: D1.1 R15.2 | length 2.2
  TOP w0.203: D1.1@11.52,31.394 R15.2@13.738,31.394
N17026648: D2.1 R19.2 | length 2.2
  TOP w0.203: D2.1@11.52,29.4 R19.2@13.738,29.4
N17026724: D3.1 R21.2 | length 2.2
  TOP w0.203: D3.1@11.52,26.3 R21.2@13.738,26.3
N17064279: Q2.3 R20.2 U6.2 | length 7.8
  TOP w0.508: U6.2@15.2,40.374 15.374,40.2 Q2.3@21.1,40.2 21.862,39.438 R20.2@21.862,38.7
N17081273: D4.1 K1.2 Q3.3 | length 12
  TOP w0.508: K1.2@73.92,85.06 79.44,85.06 81.1,83.4 81.1,80.95 D4.1@81.15,80.9 81,80.75 Q3.3@81,79.4
N17083179: D5.1 K2.2 Q4.3 | length 16.1
  TOP w0.508: Q4.3@14.65,79 D5.1@14.65,80.8 24.1,80.8 25.62,82.32 K2.2@25.62,85.06
N17083774: C16.2 D7.2 L1.1 U7.6
N17083776: C16.1 U7.1 | length 1.9
  TOP w0.508: C16.1@133.962,73.8 134.5,74.338 U7.1@134.5,75.49
N17083890: R25.2 R26.1 U7.3 | length 3.8
  TOP w0.203: U7.3@134.5,77.39 136.488,77.39 R26.1@136.738,77.64 R25.2@136.738,76.2
N17083894: R24.2 U7.4 | length 2.8
  TOP w0.203: U7.4@131.9,77.39 132.252,77.39 R24.2@133.962,79.1
N17083932: R26.2 R27.1 | length 1.5
  TOP w0.203: R26.2@138.262,77.64 R27.1@138.262,79.1
N17085874: Q1.3 R6.2 R7.2 R8.2 R10.2 | length 7.6
  TOP w0.508: R6.2@103.862,29.7 R7.2@103.862,31.1 R8.2@103.862,32.5 R10.2@103.862,33.9 107,33.9 Q1.3@107.2,33.7
N170859511: Q1.1 R12.2 | length 5.2
  TOP w0.203: Q1.1@106.2,31.3 106.2,31.5 107,32.3 109.1,32.3 110.3,31.1 R12.2@110.338,31.1
NRST: C8.1 J2.5 R14.2 U1.7 U3.31 | length 164.9
  TOP w0.203: U3.31@79.8,54.102 79.802,54.1 v1(82.8,54.1) ; v1(108.5,46.1) 108.95,45.65 U1.7@108.95,43.65
  TOP w0.254: C8.1@106.3,38.462 R14.2@107.7,38.462 108.354,38.462 108.95,39.058 U1.7@108.95,43.65
  BOTTOM w0.203: J2.5@28.74,26.762 81.362,26.762 82.8,28.2 v1(82.8,54.1) 82.8,70.8 83.8,71.8 95.9,71.8 98.5,69.2 98.5,53.8 100.1,52.2 110.697,52.2 111.7,51.197 111.7,47.2 111.293,46.793 110.026,46.793 110.02,46.8 109.2,46.8 v1(108.5,46.1)
OSC_IN: U1.5 X1.1 | length 10.2
  TOP w0.203: X1.1@101.9,37.7 102,37.8 102,38.5 103.05,39.55 103.05,39.95 103.8,40.7 106.7,40.7 107.95,41.95 U1.5@107.95,43.65
OSC_OUT: U1.6 X1.3 | length 10.1
  TOP w0.203: X1.3@104.3,37.7 104.3,38.5 103.5,39.3 103.5,39.8 103.9,40.2 106.907,40.2 108.45,41.743 U1.6@108.45,43.65
SPI1_MISO: U1.22 U2.2 | length 12.3
  TOP w0.203: U1.22@115.55,48.25 117.05,48.25 117.86,47.44 122.26,47.44 124.1,45.6 126.715,45.6 U2.2@126.75,45.565
SPI1_MOSI: U1.23 U2.5 | length 3.6
  TOP w0.203: U1.23@115.55,48.75 117.75,48.75 118.395,48.105 U2.5@118.85,48.105
SPI1_SCK: U1.21 U2.6 | length 3.7
  TOP w0.203: U1.21@115.55,47.75 116.85,47.75 117.765,46.835 U2.6@118.85,46.835
SWCLK: J3.2 R22.2 U1.49 | length 112.9
  TOP w0.203: J3.2@3.8,57.96 2.287,59.473 2.287,61.813 2.668,62.194 4.868,62.194 7.068,64.394 68.8,64.394 72.194,61 83.225,61 85.832,58.394 98.406,58.394 100.6,56.2 102.9,56.2 103.662,55.438 R22.2@103.662,55.35 103.85,55.162 U1.49@103.85,53.25
SWDIO: J3.3 R23.2 U1.46 | length 118.6
  TOP w0.203: J3.3@3.8,55.42 1.881,57.339 1.881,61.981 2.5,62.6 4.7,62.6 6.9,64.8 69.1,64.8 72.4,61.5 83.3,61.5 86,58.8 R23.2@102.138,58.8 102.938,58 106.1,58 106.95,57.15 U1.46@106.95,55.35
T_CS: J2.33 U1.2 U5.15 | length 229.1
  TOP w0.203: U1.2@106.45,43.65 v1(106.45,46.1) 106.437,46.1 104.8,44.463 104.8,43.5 104.3,43 100.5,43 99.3,41.8 99.3,35.8 100,35.1 109.544,35.1 112.8,31.844 112.8,25.7 114.906,23.594 122.968,23.594 123.806,24.432 123.806,28.468 122.275,30 115.506,30 115.2,29.694 115.2,29.1 115.498,28.802 U5.15@116.5,28.802
  BOTTOM w0.203: J2.33@28.74,62.322 27.456,61.038 24.928,61.038 23.6,59.71 23.6,18.8 26,16.4 105.7,16.4 108.9,19.6 108.9,43.65 v1(106.45,46.1)
T_MISO: J2.29 U1.10 U5.12 | length 210.5
  TOP w0.203: v1(110.923,46.1) 110.923,45.49 110.45,45.017 U1.10@110.45,43.65 110.45,37.964 114.3,34.114 114.3,28.346 115.794,26.852 U5.12@116.5,26.852
  BOTTOM w0.203: J2.29@28.74,57.242 31.9,57.242 33.663,59.005 33.663,62.995 31.895,64.763 24.305,64.763 21.427,61.885 21.427,17.89 25.09,14.227 106.61,14.227 110.923,18.54 v1(110.923,46.1)
T_MOSI: J2.30 U1.11 U5.14 | length 218.8
  TOP w0.203: v1(111.66,46.1) 111.66,45.49 110.95,44.781 U1.11@110.95,43.65 110.95,38.172 114.794,34.328 114.794,28.606 115.248,28.152 U5.14@116.5,28.152
  BOTTOM w0.203: J2.30@26.2,57.242 27.456,55.986 31.686,55.986 34.4,58.7 34.4,63.3 32.2,65.5 24,65.5 20.69,62.19 20.69,17.584 24.784,13.49 106.916,13.49 111.66,18.234 v1(111.66,46.1)
T_PEN: J2.31 R16.2 U1.9 U5.11 | length 206.6
  TOP w0.203: v1(110.187,46.1) 110.187,45.49 109.95,45.254 U1.9@109.95,43.65 109.95,37.757 113.8,33.907 113.8,28.196 115.794,26.202 U5.11@116.5,26.202 118.54,26.202 R16.2@119.038,26.7
  BOTTOM w0.203: J2.31@28.74,59.782 28.78,59.742 32.342,59.742 32.927,60.327 32.927,62.69 31.59,64.027 24.61,64.027 22.163,61.58 22.163,18.195 25.395,14.963 106.305,14.963 110.187,18.845 v1(110.187,46.1)
T_SCK: J2.34 U1.8 U5.16 | length 206.2
  TOP w0.203: v1(109.45,46.1) U1.8@109.45,43.65 109.45,37.55 113.3,33.7 113.3,25.9 115.2,24 122.8,24 123.4,24.6 123.4,28.3 122.2,29.5 116.548,29.5 U5.16@116.5,29.452
  BOTTOM w0.203: J2.34@26.2,62.322 24.622,62.322 22.9,60.6 22.9,18.5 25.7,15.7 106,15.7 109.45,19.15 v1(109.45,46.1)
USART1_RX: J4.4 U1.43 | length 111.1
  TOP w0.203: J4.4@3.8,64.88 4.72,65.8 69.5,65.8 72.796,62.504 83.704,62.504 86.107,60.1 106.607,60.1 108.45,58.257 U1.43@108.45,55.35
USART1_TX: J4.3 U1.42 | length 112
  TOP w0.203: J4.3@3.8,67.42 4.92,66.3 69.7,66.3 73.043,62.957 83.957,62.957 86.314,60.6 106.814,60.6 108.95,58.464 U1.42@108.95,55.35
USART2_RX: J1.2 U1.17 | length 84.3
  TOP w0.203: U1.17@115.55,45.75 115.55,43.718 120.862,38.406 144.032,38.406 146.013,40.387 146.013,73.237 J1.2@134.75,84.5
USART2_TX: J1.1 U1.16 | length 84.3
  TOP w0.203: U1.16@113.45,43.65 115.044,43.65 120.694,38 144.2,38 146.419,40.219 146.419,75.331 J1.1@137.25,84.5
VCC_3.3V: C1.1 C2.2 C3.2 C4.2 C5.2 C7.2 C9.2 C10.1 C11.1 C12.1 C17.1 C18.1 J1.4 J2.24 J2.25 J2.28 J3.4 J4.2 L1.2 R2.1 R3.2 R4.2 R9.2 R14.1 R15.1 R16.1 R17.2 R18.2 R19.1 R20.1 R21.1 R23.1 R25.1 SW1.1 SW1.2 TP1.1 U1.1 U1.19 U1.32 U1.48 U1.64 U2.3 U2.7 U2.8 U3.6 U3.32 U3.33 U4.8 U5.1 U5.9 U5.10 U6.1 | length 269.2
  TOP w0.203: 138.2,74.3 138.262,74.362 R25.1@138.262,76.2
  TOP w0.254: C4.2@103.662,42.2 v1(104.8,42.2) 105.5,42.2 105.95,42.65 U1.1@105.95,43.65 ; C2.2@103.662,57.1 v1(104.8,57.1) 105.5,57.1 105.95,56.65 U1.48@105.95,55.35 ; R23.1@103.662,58.8 v1(104.8,58.8) ; v1(103.85,45.05) U1.64@103.85,45.75 ; C10.1@107.962,29.452 U5.1@110.9,29.452 ; U1.19@115.55,46.75 116.55,46.75 117.7,45.6 118.815,45.6 U2.7@118.85,45.565 ; U1.32@115.55,53.25 117.088,53.25 C5.2@118.038,52.3 ; U5.9@116.5,24.902 118.738,24.902 C9.2@119.038,25.202 118.688,25.552 U5.10@116.5,25.552
  TOP w0.508: J3.4@3.8,52.88 5.622,54.702 J2.28@26.2,54.702 ; U6.1@10.2,40.374 12.074,38.5 20.138,38.5 R20.1@20.338,38.7 20.338,32.238 19.4,31.3 15.356,31.3 R15.1@15.262,31.394 R19.1@15.262,29.4 R21.1@15.262,26.3 ; v1(77.002,34.102) U3.6@79.8,34.102 ; U3.32@79.8,54.902 77.398,54.902 v1(77.002,55.298) 77.406,55.702 U3.33@79.8,55.702 ; R4.2@103.862,28.3 R3.2@103.862,26.9 106.462,26.9 v1(107.962,28.4) C10.1@107.962,29.452 ; R14.1@107.7,36.938 108.2,36.438 v1(108.2,36) ; R9.2@116.662,38.462 116.7,38.5 v1(117.7,38.5) ; v1(116.91,55.49) R17.2@118.038,55.49 ; R18.2@118.038,53.9 C5.2@118.038,52.3 118.038,52.224 C7.2@119.562,50.7 ; U2.8@118.85,44.295 120.095,44.295 120.1,44.3 ; U2.7@118.85,45.565 119.935,45.565 120.3,45.2 ; C9.2@119.038,25.202 120.536,26.7 R16.1@120.562,26.7 v1(121.7,26.7) ; v1(119.562,49.738) C7.2@119.562,50.7 ; U4.8@121.4,50.7 C7.2@119.562,50.7 ; v1@121.7,43.4 v1(121.9,43.4) 124.1,43.4 125.226,42.274 R2.1@125.226,42.2 ; v1(121.9,48.2) 123.6,48.2 124.965,46.835 U2.3@126.75,46.835
  BOTTOM w0.508: J4.2@3.8,69.96 3.76,69.96 1.9,68.1 1.9,54.78 J3.4@3.8,52.88 3.8,42 5.4,40.4 10.174,40.4 U6.1@10.2,40.374 ; J2.24@26.2,49.622 J2.25@28.74,52.162 J2.28@26.2,54.702 ; v1(77.002,34.102) v1(77.002,55.298) 77.002,65.602 77.1,65.7 ; v1(103.85,45.05) 103.85,43.15 v1(104.8,42.2) 106.8,42.2 108.2,40.8 v1(108.2,36) 108.2,28.638 v1(107.962,28.4) ; v1(104.8,58.8) v1(104.8,57.1) 119.5,57.1 119.6,57 ; v1(116.91,55.49) 119.59,55.49 119.6,55.5 ; J1.4@129.75,84.5 131.65,82.6 136.3,82.6 138.1,80.8 v1(138.1,68.9) ; SW1.1@130.75,27.7 SW1.2@143.25,27.7
  BOTTOM w1.27: J2.25@28.74,52.162 30.562,52.162 30.6,52.2
  other v1: 107.4,21.2 108.2,21.2 113.9,21.3 115.3,21.3 107.4,22.4 108.2,22.4 113.9,22.5 115.3,22.5 120.9,43.4 120.9,44.2 121.9,44.2 120.9,45 121.9,45 78.1,65.7 78.8,65.7 78.1,66.4 78.8,66.4 78.8,67.1 137.3,67.3 138.1,67.3 138.9,67.3 78.8,67.8 137.3,68.1 138.1,68.1 138.9,68.1 137.3,68.9 138.9,68.9
VCC_12V: C13.1 C14.1 C15.1 C19.1 D4.2 D5.2 D6.3 DC1.1 K1.1 K1.5 K1.6 K2.1 K2.5 K2.6 R24.1 U7.5 | length 47
  TOP w0.203: 130.2,79.2 130.3,79.1 R24.1@132.438,79.1
  TOP w0.508: K2.6@18,74.9 12.4,74.9 11.15,76.15 C14.1@11.15,78.5 D5.2@11.15,80.8 11.15,84.05 12.16,85.06 K2.5@18,85.06 ; K1.5@66.3,85.06 66.3,82.3 67.7,80.9 D4.2@77.65,80.9 77.338,80.588 C13.1@77.338,78.9 77.338,76.162 77.4,76.1 ; 130.3,76.4 130.34,76.44 131.16,76.44 ; 130.5,77.1 131.16,76.44 ; U7.5@131.9,76.44 131.16,76.44
VCC_12V_PUMP1: J5.2 K1.3 | length 2.5
  TOP w0.254: 65.2,86.3 67.7,86.3
VCC_12V_PUMP2: J6.2 K2.3
VDDA: C6.2 R9.1 U1.13 | length 7.6
  TOP w0.254: U1.13@111.95,43.65 111.95,39.812 113.3,38.462 C6.2@113.7,38.462 R9.1@115.138,38.462
VSSA: C6.1 R13.1 U1.12 | length 9.3
  TOP w0.254: U1.12@111.45,43.65 111.45,38.788 113.3,36.938 C6.1@113.7,36.938 R13.1@115.138,36.938
WK_UP: SW1.3 SW1.4 U1.14 | length 65.8
  TOP w0.203: U1.14@112.45,43.65 112.45,40.65 113.7,39.4 118,39.4 120.3,37.1 144.5,37.1 146.8,34.8 146.8,26.25 SW1.4@143.25,22.7 SW1.3@130.75,22.7
X+: U3.12 U5.2 | length 59.2
  TOP w0.203: U3.12@79.8,38.902 73.602,38.902 72.923,38.223 72.923,27.177 75.727,24.373 105.173,24.373 109.602,28.802 U5.2@110.9,28.802
X-: U3.14 U5.4 | length 62.1
  TOP w0.203: U3.14@79.8,40.502 74.002,40.502 72.074,38.574 72.074,26.826 75.376,23.524 105.524,23.524 109.502,27.502 U5.4@110.9,27.502
Y+: U3.13 U5.3 | length 60.6
  TOP w0.203: U3.13@79.8,39.702 73.802,39.702 72.498,38.398 72.498,27.002 75.552,23.948 105.348,23.948 109.552,28.152 U5.3@110.9,28.152
Y-: U3.15 U5.5 | length 63.6
  TOP w0.203: U3.15@79.8,41.302 74.202,41.302 71.65,38.75 71.65,26.65 75.2,23.1 105.7,23.1 109.452,26.852 U5.5@110.9,26.852
pads on no net: J2.32 K1.4 K2.4 U1.3 U1.4 U1.45 U3.21 U5.13

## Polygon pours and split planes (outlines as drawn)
GND on TOP "TOP-GND" (solid, pour order 415): -0.05,0 0,-0.05 150,-0.05 150.05,0 150.05,90 150,90.05 0,90.05 -0.05,90
GND on TOP "TOP-GND 1" (solid, pour order 184): 18 vertices, not listed, extent 20.25,40.95 20.732,41.45
GND on TOP "TOP-GND 2" (solid, pour order 187): 109.977,26.183 110.125,26.052 110.932,26.202 110.125,26.352 109.977,26.221 109.975,26.21 109.975,26.199 109.976,26.188 109.977,26.183
GND on TOP "TOP-GND 3" (solid, pour order 185): 111.823,26.221 111.675,26.352 110.868,26.202 111.675,26.052 111.823,26.183 111.825,26.194 111.825,26.205 111.824,26.216 111.823,26.221
GND on TOP "TOP-GND 4" (solid, pour order 183): 18 vertices, not listed, extent 15.018,77.75 15.5,78.25
GND on TOP "TOP-GND 5" (solid, pour order 117): 15.094,77.558 15.25,77.75 15.05,78.032 14.85,77.75 15.007,77.558 15.017,77.554 15.028,77.552 15.039,77.551 15.05,77.55 15.061,77.551 15.072,77.552 15.083,77.554 15.093,77.558 15.094,77.558
GND on TOP "TOP-GND 6" (solid, pour order 126): 103.102,46.231 103.25,46.1 103.882,46.25 103.25,46.4 103.102,46.269 103.1,46.258 103.1,46.247 103.101,46.236 103.102,46.231
GND on TOP "TOP-GND 7" (solid, pour order 120): 106.469,54.602 106.6,54.75 106.45,55.382 106.3,54.75 106.431,54.602 106.442,54.6 106.453,54.6 106.464,54.601 106.469,54.602
GND on TOP "TOP-GND 8" (solid, pour order 109): 25 vertices, not listed, extent 116.685,44.868 117.115,45.278
GND on TOP "TOP-GND 9" (solid, pour order 104): 25 vertices, not listed, extent 116.595,52.282 116.918,52.605
GND on TOP "TOP-GND 10" (solid, pour order 180): 116.295,52.781 116.15,52.9 115.525,52.75 116.15,52.6 116.295,52.719 116.297,52.727 116.299,52.736 116.3,52.745 116.3,52.754 116.299,52.763 116.298,52.771 116.295,52.78 116.295,52.781
GND on TOP "TOP-GND 11" (solid, pour order 129): 114.802,46.231 114.95,46.1 115.582,46.25 114.95,46.4 114.802,46.269 114.8,46.258 114.8,46.247 114.801,46.236 114.802,46.231
GND on TOP "TOP-GND 12" (solid, pour order 130): 116.298,46.269 116.15,46.4 115.518,46.25 116.15,46.1 116.298,46.231 116.3,46.242 116.3,46.253 116.299,46.264 116.298,46.269
GND on TOP "TOP-GND 13" (solid, pour order 374): 83 vertices, not listed, extent 103.191,24.932 105.911,26.189
GND on TOP "TOP-GND 14" (solid, pour order 382): 201 vertices, not listed, extent 117.698,24.559 122.841,28.941
GND on TOP "TOP-GND 15" (solid, pour order 403): 356 vertices, not listed, extent 74.559,26.059 101.585,41.445
GND on TOP "TOP-GND 16" (solid, pour order 390): 172 vertices, not listed, extent 92.36,35.253 103.123,46.191
GND on TOP "TOP-GND 17" (solid, pour order 378): 241 vertices, not listed, extent 111.811,44.209 114.991,47.513
GND on TOP "TOP-GND 18" (solid, pour order 375): 85 vertices, not listed, extent 116.583,49.687 118.837,52.666
GND on TOP "TOP-GND 19" (solid, pour order 405): 530 vertices, not listed, extent 116.109,38.965 145.454,55.441
GND on TOP "TOP-GND 20" (solid, pour order 380): 254 vertices, not listed, extent 104.255,53.309 112.885,56.499
GND on TOP "TOP-GND 21" (solid, pour order 396): 352 vertices, not listed, extent 117.468,49.559 143.615,57.741
GND on TOP "TOP-GND 22" (solid, pour order 376): 49 vertices, not listed, extent 99.637,56.759 102.805,58.241
GND on TOP "TOP-GND 23" (solid, pour order 377): 236 vertices, not listed, extent 132.874,74.146 137.703,77.553
GND on TOP "TOP-GND 24" (solid, pour order 406): 339 vertices, not listed, extent 111.086,55.654 145.454,79.053
GND on TOP "TOP-GND 25" (solid, pour order 388): 242 vertices, not listed, extent 11.861,75.611 16.1,84.349
GND on TOP "TOP-GND 26" (solid, pour order 408): 78 vertices, not listed, extent 27.5,77.057 64.3,89.7
GND on TOP "TOP-GND 27" (solid, pour order 407): 110 vertices, not listed, extent 75.7,78.404 143.6,89.7
GND on TOP "TOP-GND 28" (solid, pour order 383): 255 vertices, not listed, extent 104.607,27.611 110.078,33.189
GND on TOP "TOP-GND 29" (solid, pour order 387): 404 vertices, not listed, extent 99.859,35.659 108.366,42.441
GND on TOP "TOP-GND 30" (solid, pour order 399): 306 vertices, not listed, extent 1.559,31.953 20.3,42.707
GND on TOP "TOP-GND 31" (solid, pour order 395): 225 vertices, not listed, extent 86.743,50.309 103.291,57.835
GND on TOP "TOP-GND 32" (solid, pour order 400): 244 vertices, not listed, extent 2.846,55.413 25.464,63.835
GND on TOP "TOP-GND 33" (solid, pour order 392): 85 vertices, not listed, extent 115.692,66.257 129.608,77.643
GND on TOP "TOP-GND 34" (solid, pour order 404): 585 vertices, not listed, extent 75.7,77.057 139.741,86.041
GND on TOP "TOP-GND 35" (solid, pour order 413): 549 vertices, not listed, extent 0.3,61.659 102.148,89.7
VCC_3.3V on TOP "TOP-VCC_3.3V" (solid, pour order 381): 119.8,45.3 120.141,45.641 122.259,45.641 122.5,45.4 122.5,41.7 122.4,41.6 119.8,41.6 119.8,45.3
VCC_3.3V on TOP "TOP-VCC_3.3V 1" (solid, pour order 385): 115.4,22.9 115.8,22.5 115.8,20.9 115.5,20.6 107.5,20.6 107.1,21 107.1,22.6 107.4,22.9 115.4,22.9
VCC_3.3V on TOP "TOP-VCC_3.3V 2" (solid, pour order 398): 56 vertices, not listed, extent 76.4,64.3 140.3,74.5
VCC_3.3V on TOP "TOP-VCC_3.3V 3" (solid, pour order 251): 104.646,26.987 104.262,27.3 103.798,26.9 104.262,26.5 104.646,26.813 104.653,26.834 104.658,26.856 104.661,26.878 104.662,26.9 104.661,26.922 104.658,26.944 104.653,26.966 104.647,26.987 104.646,26.987
VCC_3.3V on TOP "TOP-VCC_3.3V 4" (solid, pour order 249): 103.775,27.684 103.462,27.3 103.862,26.836 104.262,27.3 103.949,27.684 103.928,27.691 103.906,27.696 103.884,27.699 103.862,27.7 103.84,27.699 103.818,27.696 103.796,27.691 103.775,27.685 103.775,27.684
VCC_3.3V on TOP "TOP-VCC_3.3V 5" (solid, pour order 248): 103.949,27.515 104.262,27.9 103.862,28.363 103.462,27.9 103.775,27.515 103.796,27.509 103.818,27.504 103.84,27.501 103.862,27.5 103.884,27.501 103.906,27.504 103.928,27.509 103.949,27.515
VCC_3.3V on TOP "TOP-VCC_3.3V 6" (solid, pour order 264): 108.049,28.668 108.362,29.052 107.962,29.516 107.562,29.052 107.875,28.668 107.896,28.661 107.918,28.656 107.94,28.653 107.962,28.652 107.984,28.653 108.006,28.656 108.028,28.661 108.049,28.668
VCC_3.3V on TOP "TOP-VCC_3.3V 7" (solid, pour order 232): 21 vertices, not listed, extent 107.93,29.052 108.762,29.852
VCC_3.3V on TOP "TOP-VCC_3.3V 8" (solid, pour order 188): 109.977,29.433 110.125,29.302 110.932,29.452 110.125,29.602 109.977,29.471 109.975,29.46 109.975,29.449 109.976,29.438 109.977,29.433
VCC_3.3V on TOP "TOP-VCC_3.3V 9" (solid, pour order 114): 26 vertices, not listed, extent 104.768,41.985 105.178,42.415
VCC_3.3V on TOP "TOP-VCC_3.3V 10" (solid, pour order 112): 26 vertices, not listed, extent 104.422,41.985 104.832,42.415
VCC_3.3V on TOP "TOP-VCC_3.3V 11" (solid, pour order 231): 21 vertices, not listed, extent 103.63,41.8 104.462,42.6
VCC_3.3V on TOP "TOP-VCC_3.3V 12" (solid, pour order 127): 105.969,42.902 106.1,43.05 105.95,43.682 105.8,43.05 105.931,42.902 105.942,42.9 105.953,42.9 105.964,42.901 105.969,42.902
VCC_3.3V on TOP "TOP-VCC_3.3V 13" (solid, pour order 113): 26 vertices, not listed, extent 103.635,45.018 104.065,45.428
VCC_3.3V on TOP "TOP-VCC_3.3V 14" (solid, pour order 287): 23 vertices, not listed, extent 103.25,45 104.45,45.782
VCC_3.3V on TOP "TOP-VCC_3.3V 15" (solid, pour order 208): 120.353,50.662 120.65,50.4 121.464,50.7 120.65,51 120.353,50.738 120.351,50.716 120.35,50.694 120.352,50.672 120.353,50.662
VCC_3.3V on TOP "TOP-VCC_3.3V 16" (solid, pour order 261): 119.649,49.916 119.962,50.3 119.562,50.764 119.162,50.3 119.475,49.916 119.496,49.909 119.518,49.904 119.54,49.901 119.562,49.9 119.584,49.901 119.606,49.904 119.628,49.909 119.649,49.915 119.649,49.916
VCC_3.3V on TOP "TOP-VCC_3.3V 17" (solid, pour order 246): 120.347,50.787 119.962,51.1 119.499,50.7 119.962,50.3 120.347,50.613 120.353,50.634 120.358,50.656 120.361,50.678 120.362,50.7 120.361,50.722 120.358,50.744 120.353,50.766 120.347,50.787
VCC_3.3V on TOP "TOP-VCC_3.3V 18" (solid, pour order 262): 118.125,53.115 118.438,53.5 118.038,53.963 117.638,53.5 117.951,53.115 117.972,53.109 117.994,53.104 118.016,53.101 118.038,53.1 118.06,53.101 118.082,53.104 118.104,53.109 118.125,53.115
VCC_3.3V on TOP "TOP-VCC_3.3V 19" (solid, pour order 296): 27 vertices, not listed, extent 117.638,51.57 118.692,52.7
VCC_3.3V on TOP "TOP-VCC_3.3V 20" (solid, pour order 265): 117.951,53.084 117.638,52.7 118.038,52.236 118.438,52.7 118.125,53.084 118.104,53.091 118.082,53.096 118.06,53.099 118.038,53.1 118.016,53.099 117.994,53.096 117.972,53.091 117.951,53.085 117.951,53.084
VCC_3.3V on TOP "TOP-VCC_3.3V 21" (solid, pour order 125): 116.298,53.269 116.15,53.4 115.518,53.25 116.15,53.1 116.298,53.231 116.3,53.242 116.3,53.253 116.299,53.264 116.298,53.269
VCC_3.3V on TOP "TOP-VCC_3.3V 22" (solid, pour order 238): 125.653,46.797 125.95,46.535 126.814,46.835 125.95,47.135 125.653,46.873 125.651,46.851 125.65,46.829 125.652,46.807 125.653,46.797
VCC_3.3V on TOP "TOP-VCC_3.3V 23" (solid, pour order 275): 17 vertices, not listed, extent 116.599,38.062 117.5,38.862
VCC_3.3V on TOP "TOP-VCC_3.3V 24" (solid, pour order 236): 119.947,44.333 119.65,44.595 118.787,44.295 119.65,43.995 119.947,44.257 119.949,44.279 119.95,44.301 119.948,44.323 119.947,44.333
VCC_3.3V on TOP "TOP-VCC_3.3V 25" (solid, pour order 245): 21 vertices, not listed, extent 117.715,45.265 118.882,45.865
